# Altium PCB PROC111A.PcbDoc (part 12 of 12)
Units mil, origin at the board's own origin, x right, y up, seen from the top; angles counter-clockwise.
Board outline 7700 x 2300 mil, 6 copper layers (Top Layer, GND 1, SIG 1, SIG 2, GND 2, Bottom Layer), stack 61.062 mil thick; 841 components, 632 nets, 2914 pads, 1627 vias.
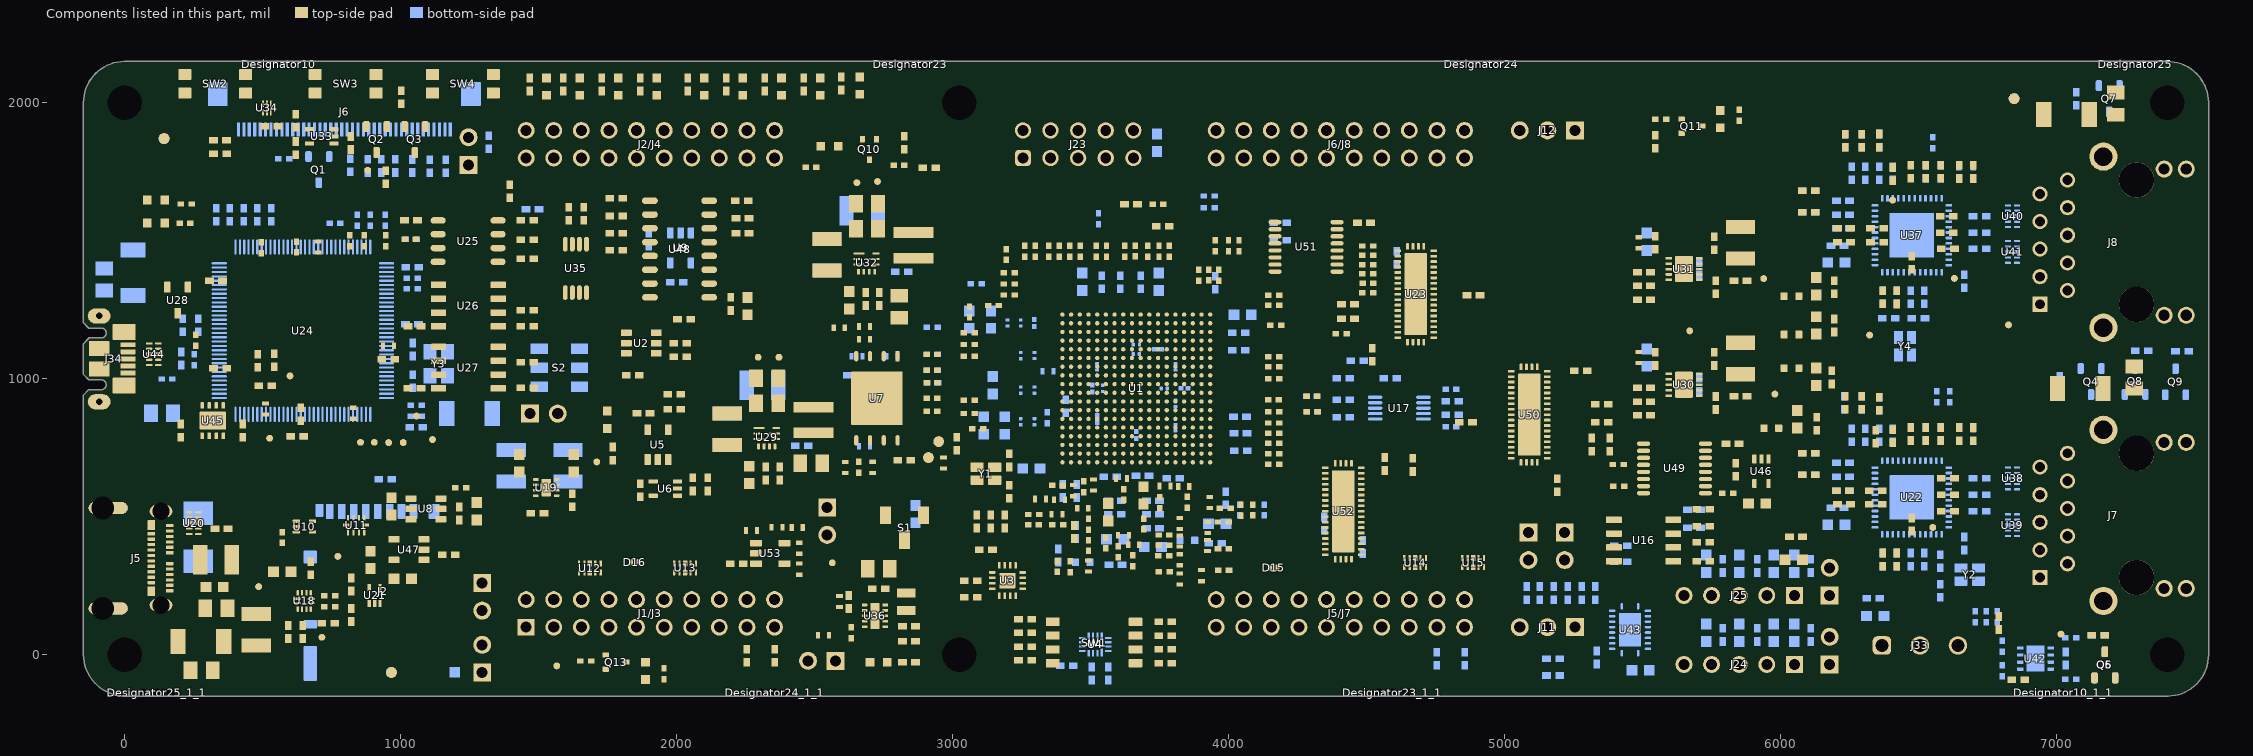
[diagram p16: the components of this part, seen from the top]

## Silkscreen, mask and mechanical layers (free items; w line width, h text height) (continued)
LP Logo:
  drawing of 8965 lines, arcs and shapes, not listed
  text "4" at 6389.42,574 h30
  text "6" at 6526.42,574 h30
  text "4" at 6048.42,485 h30
  text "6" at 5918.42,484 h30
  text "6" at 6105.42,483 h30
  text "4" at 5860.42,481 h30
  text "6" at 262.42,479 h30
  text "4" at 210.42,476 h30
  text "2" at 835.42,445 h30
  text "20" at 1746.42,442 h30
  text "3" at 6431.42,442 h30
  text "20" at 4245.42,438 h30
  text "2" at 3342.42,437 h30
  text "6" at 6510.42,423 h30
  text "4" at 6405.42,421 h30
  text "6" at -356.58,400 h30
  text "J2" at 1855.42,354 h30
  text "J6" at 4353.42,353 h30
  text "4" at -357.58,340 h30
  text "3" at 6049.42,340 h30
  text "3" at 5857.42,338 h30
  text "3" at -204.58,332 h30
  text "3" at 206.42,311 h30
  text "3" at 6429.42,286 h30
  text "5" at -70.58,274 h30
  text "4" at 5855.42,271 h30
  text "4" at 279.42,269 h30
  text "3" at 5717.42,269 h30
  text "B" at -423.58,251 h30
  text "J4" at 1852.42,242 h30
  text "J8" at 4350.42,241 h30
  text "6" at 5853.42,219 h30
  text "5" at 339.51,200.88 h30
  text "40" at -484.58,197 h30
  text "6" at 17.92,195 h30
  text "NOT FCC APPROVED FOR RESALE" at 6540.44,195.25 h50 r90
  text "20" at -260.58,189 h30 r270
  text "16" at 126.42,186 h30 r270
  text "19" at 1755.42,165 h30
  text "19" at 4248.42,162 h30
  text "8" at 339.51,140.88 h30
  text "FOR EVALUATION ONLY;" at 6440.49,140.27 h50 r90
  text "5" at 620.42,123 h30
  text "13" at 125.42,120 h30 r270
  text "16" at -221.58,112 h30
  text "A" at 1057.42,110 h30
  text "10" at 30.42,109 h30
  text "B" at 1362.42,90 h30
  text "13" at 4203.42,90 h30
  text "10" at 3127.42,89 h30
  text "12" at 3869.42,88 h30
  text "12" at 203.42,74 h30
  text "9" at 278.42,67 h30
  text "3" at 2326.42,63 h30
  text "5" at 4206.42,42 h30
  text "15" at -156.58,28 h30
  text "11" at -47.58,27 h30
  text "3" at 776.42,9 h30
  text "4" at 587.42,8 h30
  text "3" at 4360.42,-1 h30
  text "4" at 4209.92,-4 h30
  text "5" at 3341.09,-25.67 h30
  text "5" at 2173.42,-41 h30
  text "6" at 3120.42,-58 h30
  text "4" at 2323.42,-72 h30
  text "A" at 110.42,-112 h30
  text "97" at 57.42,-211 h30
  text "128" at 566.42,-211 h30
  text "24" at 4178.42,-231 h30
  text "6" at 4179.42,-301 h30
  text "5" at 4004.42,-305 h30
  text "16" at 5193.42,-307 h30
  text "5" at 4755.42,-341 h30
  text "4" at 4682.42,-343 h30
  text "3" at 5625.42,-356 h30
  text "4" at 5754.42,-366 h30
  text "WHEN ACTUATOR IS OPENED" at -766.5,-369 h30 r270
  text "4" at -372.58,-372 h30
  text "6" at 5754.42,-416 h30
  text "3" at 817.42,-423 h30
  text "4" at 905.42,-426 h30
  text "3" at 5624.42,-466 h30
  text "4" at 5750.42,-478 h30
  text "TEST AUTOMATION" at -507.58,-488 h30 r270
  text "3" at -379.58,-494 h30
  text "3" at 4683.42,-532 h30
  text "6" at 5749.42,-536 h30
  text "5" at 905.42,-548 h30
  text "2" at -250.58,-554 h30
  text "39" at 3425.42,-608 h30 r270
  text "42" at 3490.42,-608 h30 r270
  text "4" at 5757.42,-608 h30
  text "C" at 2246.42,-609 h30
  text "3" at 5615.42,-612 h30
  text "9" at 5183.09,-650.67 h30
  text "6" at 5754.42,-659 h30
  text "38" at 3374.42,-660 h30
  text "6" at -310.58,-662 h30
  text "8" at 5444.42,-693 h30
  text "6" at 4177.42,-729 h30
  text "5" at 4000.42,-730 h30
  text "3" at 5457.42,-738 h30
  text "4" at 5591.42,-739 h30
  text "4" at -324.58,-755 h30
  text "3" at -559.58,-777 h30
  text "6" at 5591.42,-793 h30
  text "4" at -400.58,-814 h30
  text "65" at -56.58,-818 h30
  text "32" at 666.42,-822 h30
  text "3" at 5458.42,-853 h30
  text "4" at 5592.42,-855 h30
  text "5" at -402.58,-894 h30
  text "6" at 5590.42,-906 h30
  text "64" at 56.42,-932 h30
  text "33" at 549.42,-936 h30
  text "4" at -74.58,-942 h30
  text "22" at 3379.42,-974 h30
  text "C" at 1061.42,-1036 h30
  text "www.ti.com/launchpad" at 3179.42,-1039 h30 r90
  text "21" at 3426.42,-1052 h30 r270
  text "18" at 3493.42,-1057 h30 r270
  text "3" at -124.58,-1058 h30
  text "2" at 1.42,-1061 h30
  text "5" at 4778.42,-1103 h30
  text "8" at 1823.42,-1112 h30
  text "4" at 4701.42,-1112 h30
  text "16" at 677.42,-1124 h30
  text "9" at 478.42,-1127 h30
  text "4" at 5773.42,-1144 h30
  text "5" at 1814.42,-1217 h30
  text "4" at 1922.42,-1233 h30
  text "2" at 830.42,-1254 h30
  text "20" at 4262.42,-1256 h30
  text "2" at 3332.42,-1257 h30
  text "20" at 1743.42,-1258 h30
  text "8" at 5625.42,-1276 h30
  text "Development Kit" at 2899.42,-1286 h30 r90
  text "LP-AM243" at 2848.42,-1288 h30 r90
  text "3" at 4701.42,-1306 h30
  text "5" at 5735.42,-1324 h30 r270
  text "J7" at 4351.42,-1342 h30
  text "J3" at 1847.42,-1344 h30
  text "7" at 4754.42,-1389 h30
  text "10" at 4990.42,-1391 h30
  text "J5" at 4348.42,-1454 h30
  text "J1" at 1844.42,-1456 h30
  text "8" at 473.42,-1465 h30
  text "2" at 4763.42,-1485 h30
  text "19" at 1722.42,-1537 h30
  text "19" at 4254.42,-1538 h30
  text "4" at 1714.42,-1626 h30
  text "3" at 1881.42,-1626 h30

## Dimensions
-130.32,1183.41 to -150,1999.99 on M2 Board Dimensions
-120.32,960.97 to -140,0 on M2 Board Dimensions
-84.25,1166.5 to -84.25,1253.3 on M2 Board Dimensions
-130.32,960.97 to -130.32,996.4 on M1 Board Outline
-145.84,-427.94 to 7554.16,-427.94 on M2 Board Dimensions
7418.82,2150.26 to 7400,-149.99 on M2 Board Dimensions
7545.83,5089 to 7554.16,-427.94 on M2 Board Dimensions
10072.36,-496.24 to 11072.36,-496.24 on M2 Board Dimensions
